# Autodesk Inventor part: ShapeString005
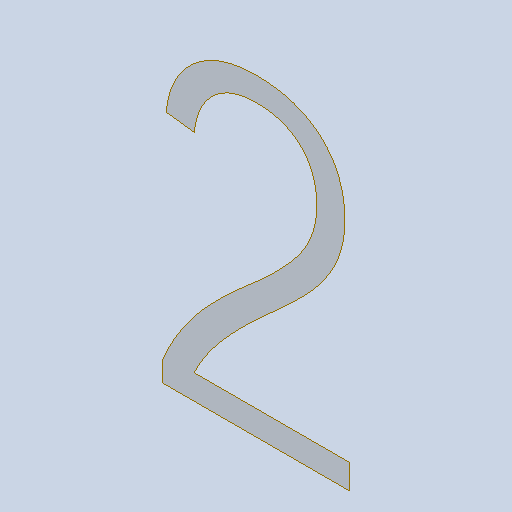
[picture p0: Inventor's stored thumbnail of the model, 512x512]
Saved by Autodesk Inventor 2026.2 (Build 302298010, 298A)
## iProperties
Created: 2026-10
Part Number: ShapeString005
Material: Générique
Document SubType Name: Modeling
Designer: mel
Density: 1 g/cm^3
Appearance: Par défaut
Author: mel
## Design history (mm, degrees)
feature "Composite1"
body "Srf1"
